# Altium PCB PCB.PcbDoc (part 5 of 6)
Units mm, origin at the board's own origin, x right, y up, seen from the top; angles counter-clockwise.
Board outline 101.6 x 101.61 mm, 4 copper layers (Top Layer, GND, POWER, Bottom Layer), stack 1.371 mm thick; 506 components, 346 nets, 1798 pads, 1471 vias.
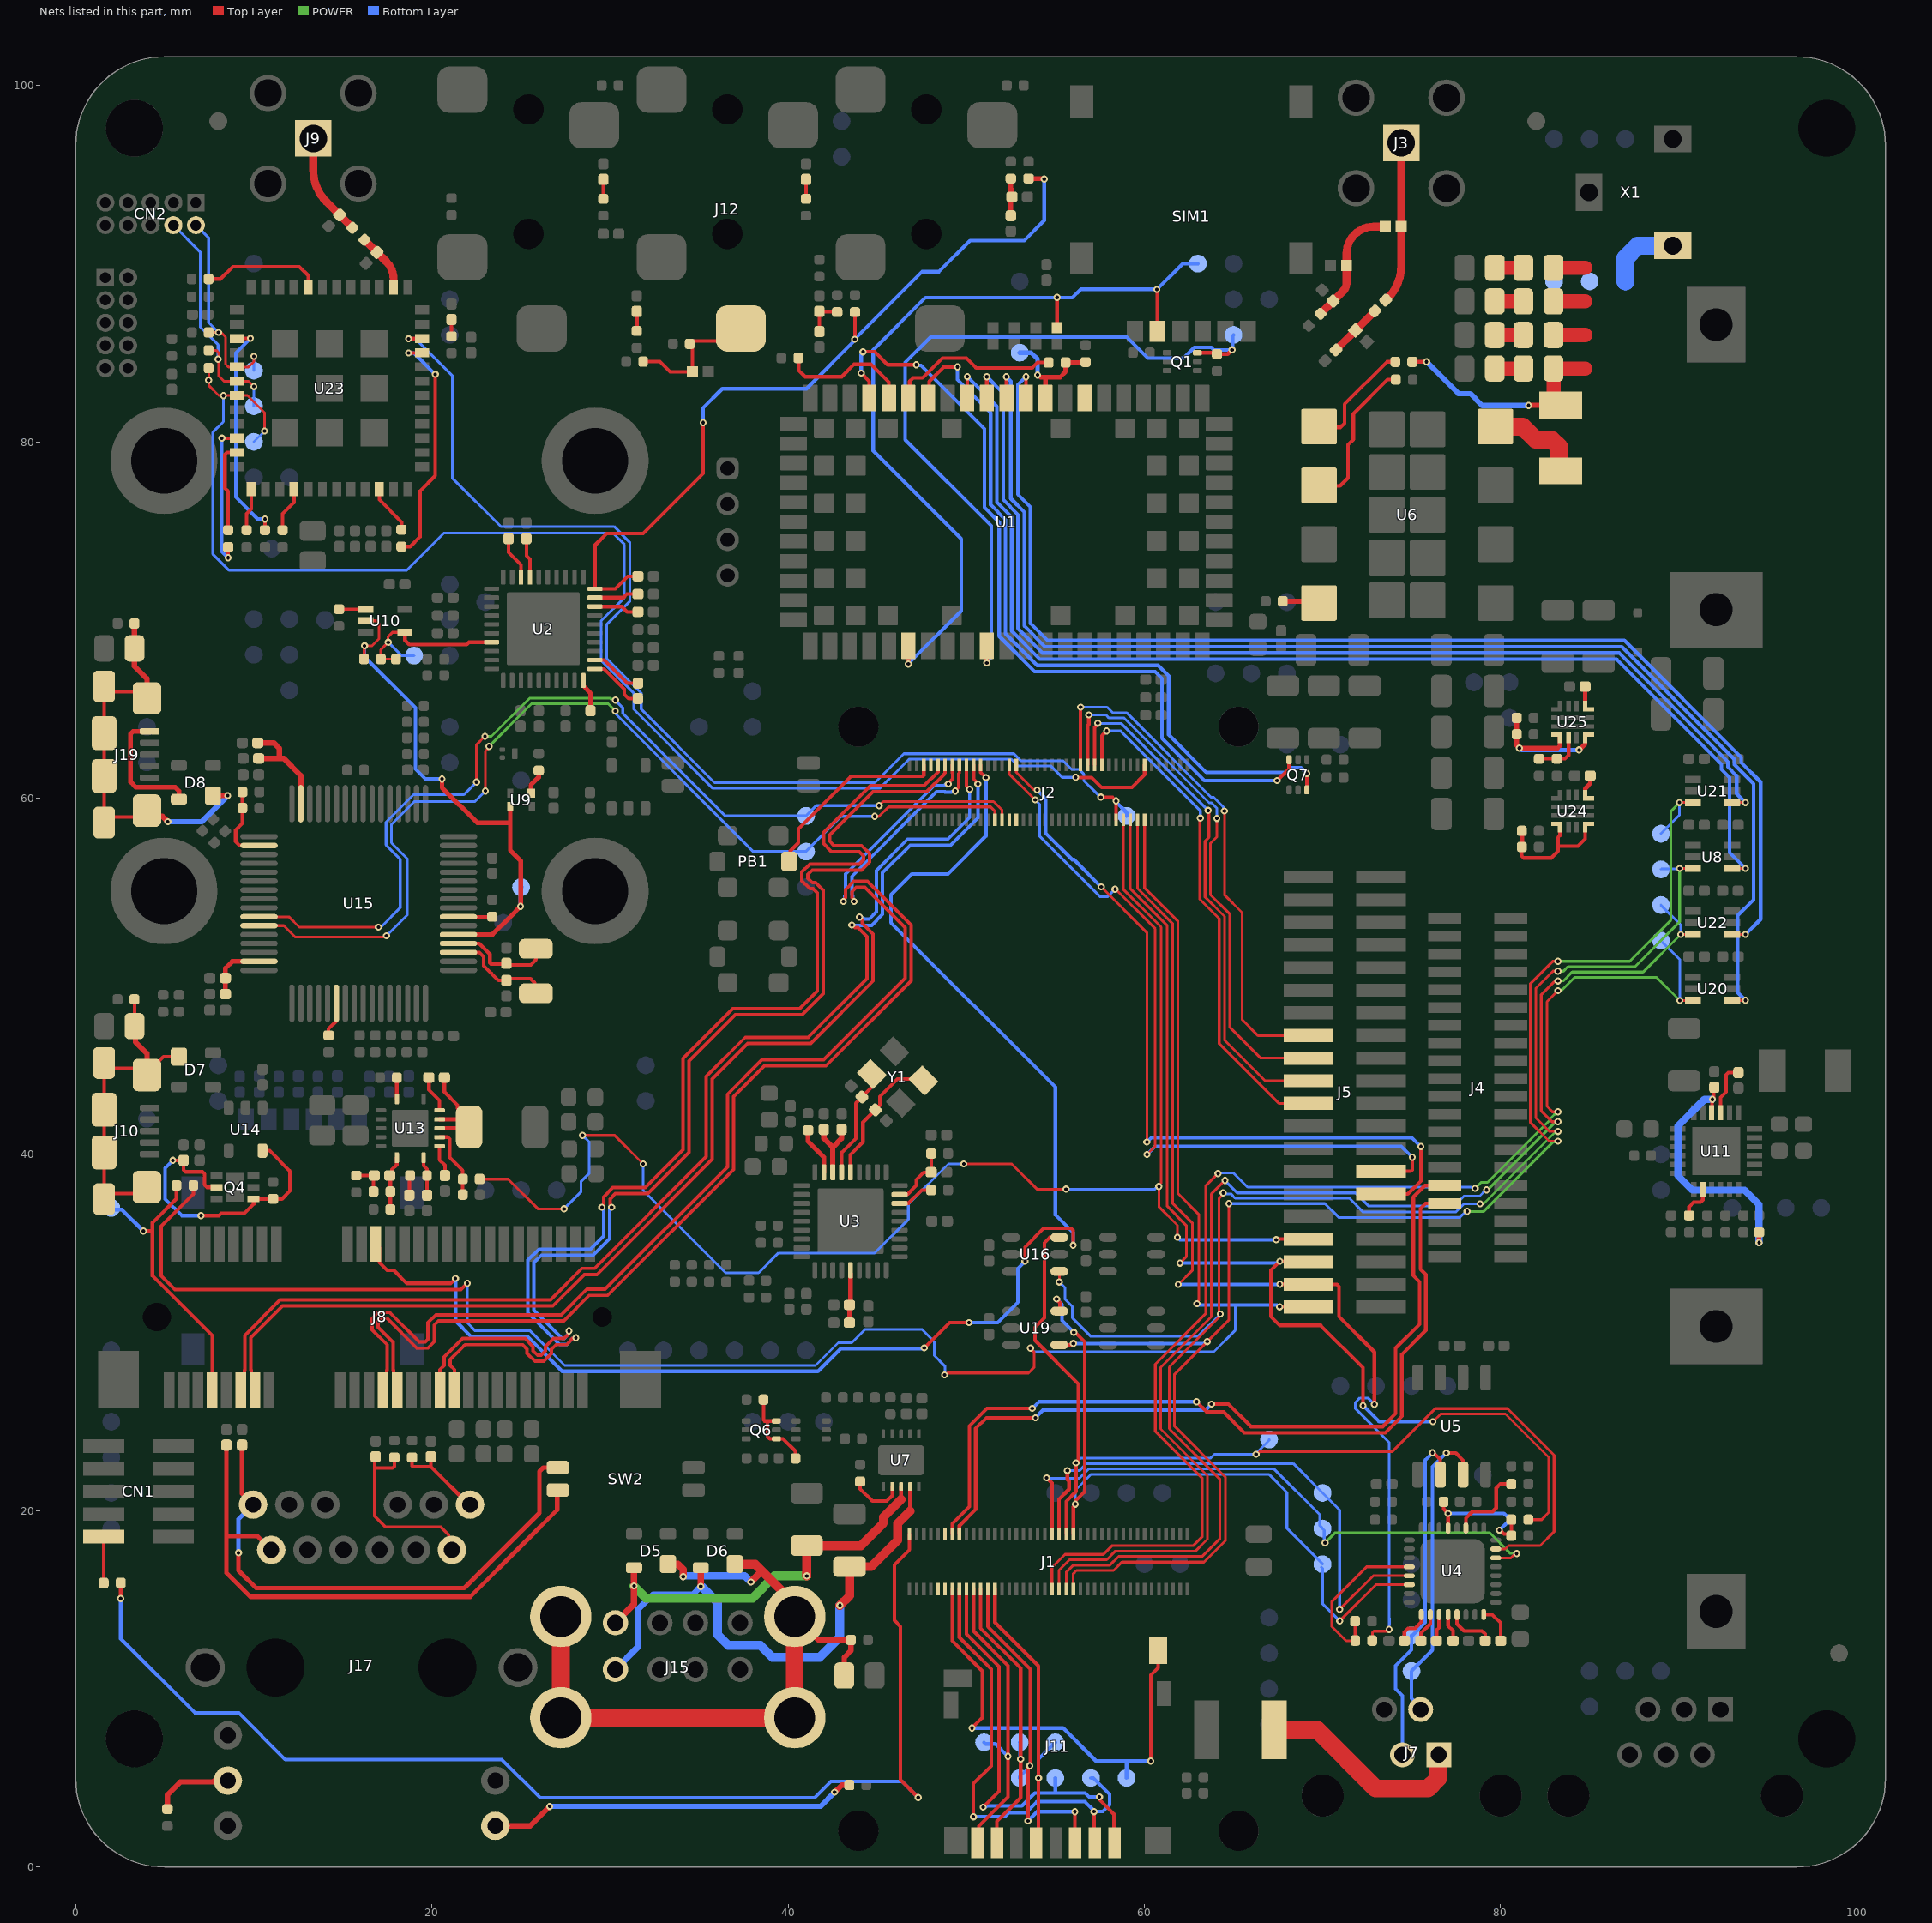
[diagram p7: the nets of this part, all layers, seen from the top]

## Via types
v1: diameter 0.4, hole 0.2, Top Layer to Bottom Layer, tented both sides, 1471 vias

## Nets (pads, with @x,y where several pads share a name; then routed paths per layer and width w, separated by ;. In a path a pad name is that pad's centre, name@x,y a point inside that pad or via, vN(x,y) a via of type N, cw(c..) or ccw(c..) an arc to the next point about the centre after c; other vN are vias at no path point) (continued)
JTAG.TRST_1: J1.80 R119.1 | length 68
  Top Layer w0.2: v1(2.528,15.071) R119.1@2.528,15.945 ; J1.80@46.81,18.685 46.81,18.376 46.81,17.81 45.963,16.963 45.963,13.845 46.308,13.5 46.308,4.892 v1(47.3,3.9)
  Bottom Layer w0.2: v1(2.528,15.071) 2.528,12.822 6.705,8.645 9.159,8.645 11.767,6.036 23.921,6.036 26.077,3.88 41.491,3.88 42.406,4.795 46.405,4.795 v1(47.3,3.9)
LICELL: J2.7
LORA_BOOT0_1: J2.67 R18.1 STM_BOOT0.X U23.43 | length 83.6
  Top Layer w0.15: R18.1@7.464,84.138 v1(7.464,83.457) 7.464,83.163 8.027,82.6 9.638,82.6 10.6,81.638 v1(10.6,80.6)
  Top Layer w0.2: v1(56.149,61.167) 56.155,61.16 57.04,61.16 57.6,60.6 59.294,60.6 60.01,61.316 J2.67@60.01,61.865
  Bottom Layer w0.15: v1(8.291,82.59) 8.291,81.129 7.7,80.539 7.7,73.69 8.597,72.794 18.594,72.794 20.674,74.873 30.164,74.873 30.805,74.231 30.805,71.261 29.501,69.956 29.501,67.721 31.333,65.888 31.333,64.98 35.753,60.56 45.16,60.56 46.79,62.19 52.517,62.19 52.908,61.799 54.761,61.799 55.393,61.167 v1(56.149,61.167) ; STM_BOOT0.X@10,80 v1(10.6,80.6)
LORA_IRQ_1: J2.60 LORA_IRQ.X U23.22 | length 64.5
  Top Layer w0.2: v1(18.687,85.788) 18.689,85.79 19.44,85.79 U23.22@19.45,85.8 ; v1(57.556,60.054) 57.578,60.032 58.216,60.032 v1(58.41,59.837) J2.60@58.41,58.785
  Bottom Layer w0.15: v1(18.687,85.788) 19.071,85.788 21.157,83.702 21.157,77.952 23.866,75.243 30.226,75.243 31.105,74.363 31.105,71.038 29.801,69.734 29.801,67.845 31.75,65.896 31.75,64.987 35.874,60.864 44.864,60.864 46.49,62.49 52.669,62.49 53.061,62.099 55.425,62.099 55.906,61.617 56.335,61.617 56.598,61.354 56.598,60.984 57.216,60.366 57.528,60.054 v1(57.556,60.054)
  Bottom Layer w0.2: v1(58.41,59.837) 58.41,59.783 59,59.193 LORA_IRQ.X@59,59
LoRa_SWCLK_6: CN2.4 LoRa_SWCLK.X R11.1 U23.42 | length 13.9
  Top Layer w0.15: R11.1@7.464,85.138 7.889,85.138 8.027,85 v1@8.027,84.674 ; v1(7.988,84.636) v1@8.027,84.674 ; v1(10,83.1) 9.7,83.4 U23.42@9.05,83.4 8.327,83.4 8.027,83.7 v1@8.027,84.674
  Bottom Layer w0.15: CN2.4@5.479,92.158 6.984,90.653 6.984,86.451 7.988,85.447 v1(7.988,84.636) ; LoRa_SWCLK.X@10,82 v1(10,83.1)
LoRa_SWDIO_6: CN2.2 LoRa_SWDIO.X R10.1 U23.41 | length 12
  Top Layer w0.15: R10.1@7.464,86.138 v1(8.016,86.138) 8.063,86.091 8.208,86.091 8.413,85.885 8.413,84.361 8.574,84.2 U23.41@9.05,84.2 9.7,84.2 10,84.5 v1(10,84.8)
  Bottom Layer w0.15: CN2.2@6.749,92.158 7.459,91.448 7.459,86.694 v1(8.016,86.138) ; LoRa_SWDIO.X@10,84 v1(10,84.8)
MCTS_1V8_5: U1.11 U20.4 | length 73.9
  Top Layer w0.15: U20.4@93,48.65 v1(93.75,48.65)
  Top Layer w0.2: U1.11@52.25,82.45 v1(52.25,83.65)
  Bottom Layer w0.2: v1(52.25,83.65) 52.5,83.4 52.5,76.812 53.25,76.062 53.25,69.666 54.416,68.5 86.8,68.5 93.132,62.168 93.132,61.873 94.2,60.805 94.2,54.3 93.3,53.4 93.3,49.1 v1(93.75,48.65)
MDTR_5: MDTR.X R7.2 R8.2 U1.9 | length 6.6
  Top Layer w0.25: v1(54,83.75) 54.041,83.75 54.165,83.625 54.45,83.625 ; U1.9@54.45,82.45 54.45,83.625 ; R7.2@56.7,84.475 56.688,84.462 55.587,84.462 R8.2@55.575,84.45 55.575,83.93 55.27,83.625 54.45,83.625
  Bottom Layer w0.25: MDTR.X@53,85 53.65,85 54,84.65 v1(54,83.75)
MICBIAS_4: C51.2 R36.1 R39.1 U2.20 | length 44.9
  Top Layer w0.2: C51.2@31.565,72.45 30.993,72.45 30.293,71.75 U2.20@29.15,71.75 29.15,74.187 29.817,74.855 31.857,74.855 35.225,78.223 v1(35.225,81.075) ; v1(43.734,85.753) 43.75,85.769 R36.1@43.75,87.275
  Top Layer w0.25: R39.1@53.5,94.775 54.35,94.775 v1(54.375,94.75)
  Bottom Layer w0.2: v1(35.225,81.075) 35.225,81.9 36.3,82.975 41.025,82.975 43.734,85.684 v1(43.734,85.753) 47.53,89.55 48.462,89.55 50.211,91.299 53.249,91.299 54.375,92.425 v1(54.375,94.75)
MRI_5: U1.7
MRST_1V8_5: Q7.6 U1.18 | length 45.8
  Top Layer w0.2: v1(44.1,83.85) 44.55,83.4 U1.18@44.55,82.45 ; v1(44.2,85.05) 44.86,85.05 45.589,84.321 v1(47.191,84.321) ; v1(67.448,60.982) 68.125,61.659 Q7.6@68.125,62.16
  Bottom Layer w0.2: v1(44.1,83.85) 44.1,84.896 44.2,84.996 v1(44.2,85.05) ; v1(47.191,84.321) 47.227,84.285 47.462,84.285 50.903,80.844 51.02,80.727 51.02,76.312 51.85,75.482 51.85,69.087 53.837,67.1 60.592,67.1 60.983,66.709 60.983,63.359 63.359,60.982 v1(67.448,60.982)
MRTS_1V8_5: U1.10 U22.4 | length 70.8
  Top Layer w0.15: U22.4@93,52.35 v1(93.75,52.35) U22.4@93,52.35
  Top Layer w0.2: U1.10@53.35,82.45 v1(53.35,83.65)
  Bottom Layer w0.2: v1(53.35,83.65) 52.9,83.2 52.9,77.052 53.6,76.352 53.6,69.811 54.561,68.85 86.945,68.85 93.509,62.286 93.509,61.991 94.6,60.9 94.6,53.2 v1(93.75,52.35)
MRX_1V8_5: U1.13 U8.4 | length 66.6
  Top Layer w0.15: U8.4@93,56.05 v1(93.75,56.05)
  Top Layer w0.2: U1.13@50.05,82.45 50.054,82.453 v1(50.054,83.654)
  Bottom Layer w0.2: v1(50.054,83.654) 51.72,81.987 51.72,76.602 52.55,75.772 52.55,69.376 54.127,67.8 86.51,67.8 92.405,61.905 92.405,61.61 92.858,61.158 92.858,56.942 v1(93.75,56.05)
MTX_1V8_5: U1.12 U21.4 | length 62.5
  Top Layer w0.15: U21.4@93,59.75 v1(93.75,59.75)
  Top Layer w0.2: U1.12@51.15,82.45 v1(51.15,83.65)
  Bottom Layer w0.2: v1(51.15,83.65) 52.07,82.73 52.07,76.747 52.9,75.917 52.9,69.521 54.271,68.15 86.655,68.15 92.755,62.05 92.755,61.755 93.25,61.26 93.25,60.25 v1(93.75,59.75)
Net12MHz_CLK_X: 12MHz_CLK.X R60.1 U9.3 U10.2 U15.5 | length 29.5
  Top Layer w0.15: R60.1@16.185,67.805 16.2,67.82 16.2,68.534 v1(16.216,68.55) 16.645,68.55 17.032,68.937 17.032,69.808 16.885,69.955 U10.2@16.285,69.955
  Top Layer w0.26: v1(20.57,61.075) 20.57,60.588 22.54,58.618 24.305,58.618 24.395,58.708 ; U15.5@21.489,52.338 23.391,52.338 24.41,53.357 v1(24.977,53.924) 24.977,56.479 24.395,57.061 24.395,58.708 ; U9.3@24.395,59.525 24.395,58.708
  Bottom Layer w0.2: v1(16.216,68.55) 16.216,67.929 19.07,65.075 19.07,61.638 19.633,61.075 v1(20.57,61.075)
  Bottom Layer w0.26: v1(24.977,53.924) 24.989,53.936 24.989,54.989 12MHz_CLK.X@25,55
NetAUDIO_MCLK_X: AUDIO_MCLK.X R60.2 R61.2 U2.37 U10.4 | length 10.6
  Top Layer w0.15: R61.2@18.085,67.805 17.235,67.805 17.135,67.905 17.135,68.335 v1(17.543,68.743) 17.543,69.063 17.785,69.305 U10.4@18.485,69.305
  Top Layer w0.2: U10.4@18.485,69.305 18.485,68.855 18.726,68.614 21.952,68.614 22.088,68.75 U2.37@23.35,68.75
  Bottom Layer w0.15: v1(17.543,68.743) 18.286,68 AUDIO_MCLK.X@19,68
NetC8_2: C8.2 C9.1 L1.2 | length 3.1
  Top Layer w0.425: C8.2@70.758,85.158 L1.2@71.85,86.25 C9.1@72.938,87.338
NetC9_2: C9.2 J3.1 L2.2 | length 9.1
  Top Layer w0.447: C9.2@73.553,87.953 73.678,88.078 ccw(c71.882,89.874) 74.422,89.874 L2.2@74.422,92.078 J3.1@74.422,96.774
NetC10_2: C10.2 D4.C L2.1 R6.2 | length 7
  Top Layer w0.447: R6.2@69.886,87.186 70.4,87.7 C10.2@70.6,87.9 71.023,88.323 71.159,88.459 ccw(c70.7,88.917) 71.348,88.885 cw(c72.463,88.831) 71.349,88.913 71.35,88.923 71.35,90.55 cw(c72.878,90.55) 72.878,92.078 L2.1@73.522,92.078
NetC16_2: C16.2 R15.1 U23.26 | length 3.3
  Top Layer w0.44: R15.1@16.216,91.334 C16.2@16.92,90.63 17.438,90.112 cw(c16.445,89.118) 17.85,89.118 U23.26@17.85,88.65
NetC17_2: C17.2 J9.1 R15.2 | length 5.8
  Top Layer w0.44: J9.1@13.335,97.028 13.335,95.267 ccw(c15.875,95.267) 14.079,93.471 C17.2@14.821,92.729 R15.2@15.545,92.006
NetC20_1: C20.1 J17.6 SW2.2 | length 32.3
  Top Layer w0.25: C20.1@8.459,23.688 8.459,18.568 ; J17.6@10.975,17.8 10.207,18.568 8.459,18.568 ; SW2.2@27.065,21.155 27.029,21.119 27.029,20.049 25.119,18.138 22.148,15.168 9.806,15.168 8.459,16.514 8.459,18.568
NetC21_1: C21.1 J17.7 R94.1 | length 5.2
  Top Layer w0.2: R94.1@18.891,22.99 18.891,22.527 18.949,22.469 19.944,22.469 ; C21.1@19.941,23.03 19.941,22.472 19.944,22.469 ; J17.7@22.14,20.34 22.072,20.34 19.944,22.469
NetC22_1: C22.1 R26.2 | length 1.1
  Top Layer w0.2: R26.2@41,93.637 C22.1@41,94.727
NetC23_1: C23.1 R27.2 | length 1.1
  Top Layer w0.25: R27.2@31.5,86.225 C23.1@31.5,87.315
NetC31_1: C31.1 U2.12 | length 3
  Top Layer w0.2: U2.12@29.15,67.75 29.663,67.75 30.963,66.45 C31.1@31.565,66.45
NetC31_2: C31.2 U2.11 | length 3.3
  Top Layer w0.2: U2.11@29.15,67.25 29.668,67.25 30.229,66.689 30.806,66.112 30.806,65.826 31.052,65.58 C31.2@31.565,65.58
NetC33_1: C33.1 U2.10 | length 1.9
  Top Layer w0.25: U2.10@28.5,66.6 28.5,66.3 28.9,65.9 C33.1@28.9,64.9
NetC34_2: C34.2 R65.2 U13.8 | length 2.2
  Top Layer w0.2: U13.8@19.53,39.815 19.53,39.371 19.725,39.176 R65.2@19.725,38.815 19.73,38.81 C34.2@19.73,37.715
NetC38_1: C38.1 R32.2 | length 0.9
  Top Layer w0.2: R32.2@21.1,85.925 C38.1@21.1,86.865
NetC41_1: C41.1 R33.2 | length 1.1
  Top Layer w0.2: R33.2@29.622,93.637 C41.1@29.622,94.727
NetC42_2: C42.2 C44.2 R37.1 | length 2.1
  Top Layer w0.2: C42.2@41.75,86.185 C44.2@41.75,87.315 41.77,87.295 42.73,87.295 R37.1@42.75,87.275
NetC45_1: C45.1 C47.2 R38.1 | length 3.1
  Top Layer w0.2: R38.1@52.5,94.775 52.5,94.274 52.565,94.209 C45.1@52.565,93.75
  Top Layer w0.25: C47.2@52.5,92.685 R38.1@52.5,94.775
NetC46_1: C46.1 U2.27 | length 2.2
  Top Layer w0.19: C46.1@25.3,74.565 25.3,73.6 25.5,73.4 U2.27@25.5,72.4
NetC48_1: C48.1 U2.18 | length 2.5
  Top Layer w0.2: U2.18@29.15,70.75 30.655,70.75 30.955,70.45 C48.1@31.565,70.45
NetC49_1: C49.1 U2.19 | length 2.5
  Top Layer w0.2: U2.19@29.15,71.25 30.739,71.25 30.939,71.45 C49.1@31.565,71.45
NetC50_1: C50.1 U2.28 | length 2.5
  Top Layer w0.19: C50.1@24.3,74.565 24.3,73.8 25,73.1 U2.28@25,72.4
NetC52_1: C52.1 J17.12 SW2.1 | length 30
  Top Layer w0.25: v1(9.139,17.638) 9.139,16.648 10.134,15.654 21.823,15.654 26.033,19.864 26.033,22.206 26.247,22.42 26.86,22.42 SW2.1@26.865,22.425 ; C52.1@9.339,23.688 9.339,20.961 J17.12@9.96,20.34
  Bottom Layer w0.25: v1(9.139,17.638) 9.139,19.519 J17.12@9.96,20.34
NetC53_1: C53.1 U4.29 | length 2.7
  Top Layer w0.2: U4.29@77.55,14.175 77.55,13.65 77.944,13.256 78.949,13.256 79.13,13.075 C53.1@79.13,12.7
NetC53_2: C53.2 U4.32 | length 2.1
  Top Layer w0.2: U4.32@79.05,14.175 79.525,14.175 80,13.7 C53.2@80,12.7
NetC54_1: C54.1 U4.27 | length 1.5
  Top Layer w0.2: C54.1@76.4,12.7 76.4,13.3 76.55,13.45 U4.27@76.55,14.175
NetC54_2: C54.2 U4.26 | length 1.7
  Top Layer w0.2: C54.2@75.53,12.7 75.53,13.13 76.05,13.65 U4.26@76.05,14.175
NetC55_1: C55.1 U4.25 | length 2.1
  Top Layer w0.2: C55.1@74.6,12.7 74.6,13.2 74.8,13.4 75.2,13.4 75.55,13.75 U4.25@75.55,14.175
NetC56_1: C56.1 U4.28 | length 1.6
  Top Layer w0.2: U4.28@77.05,14.175 77.05,13.55 77.33,13.27 C56.1@77.33,12.7
NetC65_2: C65.2 U24.7 | length 1.2
  Top Layer w0.25: U24.7@84.738,60.159 84.738,60.533 85.038,60.833 C65.2@85.038,61.259
NetC66_2: C66.2 C67.2 U3.34 | length 3.8
  Top Layer w0.3: C67.2@42,41.4 42,40.9 42.5,40.4 ; U3.34@42.5,39 42.5,40.4 ; C66.2@43,41.4 43,40.9 42.5,40.4
NetC68_2: C68.2 C69.2 U3.14 | length 3.8
  Top Layer w0.2: C68.2@43.435,30.55 C69.2@43.435,31.55
  Top Layer w0.25: C68.2@43.435,30.55 43.435,31.491 43.5,31.556 U3.14@43.5,33.3
NetC78_2: C78.2 D5.4 J15.1 U7.8 | length 23
  Top Layer w0.2: 46.339,20.638 U7.8@46.339,21.363
  Top Layer w0.35: J15.1@30.3,13.71 31.345,14.755 v1(31.345,15.778) D5.4@31.345,16.8
  Top Layer w0.5: v1(41.039,16.338) C78.2@41.039,18.038 44.073,18.038 45.339,19.304 45.339,19.637 46.339,20.638
  POWER w0.5: v1(31.345,15.778) 32.023,15.1 38.002,15.1 39.239,16.338 v1(41.039,16.338)
NetC79_2: C79.2 D6.4 J15.5 U7.9 | length 30.7
  Top Layer w0.2: 46.839,19.978 U7.9@46.839,21.363
  Top Layer w0.35: D6.4@35.095,16.8 35.095,15.752 v1(35.097,15.75)
  Top Layer w0.5: v1(42.901,14.686) 43.439,15.225 C79.2@43.439,16.863 44.664,16.863 46.142,18.34 46.142,19.28 46.839,19.978
  Bottom Layer w0.35: J15.5@30.3,11.09 31.561,12.351 31.561,14.453 32.408,15.3 34.647,15.3 v1(35.097,15.75)
  Bottom Layer w0.5: v1@35.2,15.7 36.039,14.861 36.039,13.038 36.639,12.438 38.439,12.438 39.113,11.764 41.188,11.764 41.191,11.767 41.768,11.767 42.901,12.899 v1(42.901,14.686)
NetC80_2: C80.2 D5.1 D6.1 J15.Shell R59.2 | length 42.1
  Top Layer w0.3: J15.Shell@40.37,14.06 41.68,12.75 R59.2@43.525,12.75 43.525,12.147 43.15,11.772 C80.2@43.15,10.75
  Top Layer w0.4: D5.1@33.255,17 33.808,17 34.108,16.7 v1(34.108,16.3) ; v1(37.908,16) 38.529,16.621
  Top Layer w0.5: D6.1@37.005,17 38.15,17 38.529,16.621 J15.Shell@40.37,14.78
  Top Layer w0.7: J15.Shell@40.37,14.06 J15.Shell@40.37,14.78
  Top Layer w1: J15.Shell@27.23,14.06 J15.Shell@27.23,8.38 J15.Shell@40.37,8.38 J15.Shell@40.37,14.06
  Bottom Layer w0.25: J15.Shell@40.084,14.06 J15.Shell@40.57,14.06
  Bottom Layer w0.4: v1(34.108,16.3) 34.153,16.345 37.563,16.345 v1(37.908,16)
NetC81_1: C81.1 J17.1 R93.1 | length 10.5
  Top Layer w0.19: C81.1@16.841,23.03 16.791,22.98 16.791,22.396 ; R93.1@17.891,22.99 17.891,22.499 17.787,22.396 16.791,22.396 ; J17.1@21.125,17.8 20.941,17.984 20.941,18.639 20.491,19.09 17.391,19.09 16.791,19.69 16.791,22.396
NetC82_2: C82.2 R65.1 | length 1.1
  Top Layer w0.2: C82.2@18.73,37.715 18.73,38.77 R65.1@18.775,38.815
NetC84_1: C84.1 U11.21 | length 3
  Top Layer w0.2: U11.21@92.35,42.335 92.35,43.193 92.67,43.512 92.67,44.478 92.787,44.595 C84.1@93.35,44.595
NetC89_2: C89.2 R54.1 U3.26 | length 3.5
  Top Layer w0.2: U3.26@46.25,37.75 46.265,37.765 46.698,37.765 47.2,38.268 47.2,38.575 47.46,38.835 47.612,38.987 48.012,38.987 C89.2@48.027,39.002 R54.1@48.026,40.047
NetC90_2: C90.2 U3.33 Y1.3 | length 6.3
  Top Layer w0.2: U3.33@43,39 43,40.1 43.789,40.889 43.789,42.874 C90.2@44.14,43.225 44.741,43.825 44.741,44.462 Y1.3@44.692,44.511
NetC91_2: C91.2 U3.32 Y1.1 | length 7.8
  Top Layer w0.2: U3.32@43.5,39 43.5,40 44.195,40.695 44.195,41.803 C91.2@44.892,42.501 45.142,42.751 45.142,43.242 46.128,44.228 47.52,44.228 Y1.1@47.591,44.157
NetC93_1: C93.1 U13.13 | length 2.1
  Top Layer w0.2: C93.1@19.83,44.315 19.83,43.632 20.43,43.032 U13.13@20.43,42.465
NetC93_2: C93.2 L6.1 U13.11 U13.12 | length 5.9
  Top Layer w0.2: C93.2@20.7,44.315 20.7,43.508 21.439,42.769 21.439,42.601 L6.1@21.688,42.352
  Top Layer w0.25: U13.11@20.43,41.465 22.017,41.465 L6.1@22.089,41.538 21.662,41.965 U13.12@20.43,41.965
NetC107_1: C107.1 U15.3 Y3.2 | length 6.1
  Top Layer w0.2: U15.3@21.489,51.338 22.656,51.338 22.9,51.094 22.9,50.593 23.32,50.173 23.73,49.763 C107.1@24.178,49.763 24.276,49.861 25.535,49.861 25.761,49.635 25.761,49.04 Y3.2@25.842,48.96
NetC108_2: C108.2 C109.2 U15.47 | length 3.5
  Top Layer w0.26: C109.2@8.4,49 C108.2@8.4,49.9 8.4,50.448 8.789,50.838 U15.47@10.289,50.838
NetC110_2: C110.2 C111.2 U15.31 | length 6.3
  Top Layer w0.3: C110.2@10.22,63.093 11.132,63.093 11.437,62.788 11.437,62.227 ; C111.2@10.27,62.227 11.437,62.227 ; U15.31@12.639,59.688 12.639,60.72 12.643,60.724 12.643,61.269 11.686,62.227 11.437,62.227
NetC112_1: C112.1 U15.4 Y3.1 | length 5.9
  Top Layer w0.2: U15.4@21.489,51.838 22.651,51.838 23.25,51.238 23.25,50.752 23.309,50.693 C112.1@24.178,50.693 ; C112.1@24.178,50.723 24.266,50.635 25.545,50.635 25.847,50.937 25.847,51.532 Y3.1@25.835,51.543
NetC116_1: C116.1 C121.2 | length 1.5
  Top Layer w0.8: C121.2@79.77,87.879 C116.1@81.27,87.879
NetC117_2: C117.2 Q4.A Q4.G R89.1 U14.5 | length 17.3
  Top Layer w0.2: v1(5.455,39.665) C117.2@6.055,39.665 6.055,39.137 6.172,39.019 7.117,39.019 7.235,38.902 7.235,38.299 7.379,38.155 Q4.G@7.905,38.155 ; v1(7.035,36.568) 8.051,36.568 8.173,36.689 9.473,36.689 9.985,37.201 Q4.A@9.985,37.505 R89.1@10.985,37.505 ; U14.5@10.485,40.205 10.886,40.205 12.025,39.066 12.025,37.95 11.58,37.505 R89.1@10.985,37.505
  Bottom Layer w0.2: v1(5.455,39.665) 5.025,39.235 5.025,37.495 5.952,36.568 v1(7.035,36.568)
NetC118_1: C118.1 C122.2 | length 1.5
  Top Layer w0.8: C122.2@79.77,89.761 C118.1@81.27,89.761
NetC119_1: C119.1 C123.2 | length 1.5
  Top Layer w0.8: C123.2@79.77,85.997 C119.1@81.27,85.997
NetC120_1: C120.1 C124.2 | length 1.5
  Top Layer w0.8: C124.2@79.77,84.115 C120.1@81.27,84.115
NetC127_1: C127.1 U13.9 | length 1.8
  Top Layer w0.2: U13.9@20.43,40.465 20.43,39.691 20.73,39.391 C127.1@20.73,38.815
NetC128_1: C128.1 R67.2 R68.1 U13.7 | length 3.1
  Top Layer w0.2: R67.2@17.67,36.915 R68.1@17.67,37.915 17.67,38.775 C128.1@17.63,38.815 17.751,38.936 17.751,39.146 18.03,39.426 U13.7@18.03,39.815
NetC128_2: C128.2 R64.1 R68.2 | length 1.9
  Top Layer w0.2: R64.1@15.755,38.815 C128.2@16.76,38.815 16.72,38.775 R68.2@16.72,37.915
NetC147_2: C147.2 U25.7 | length 1.1
  Top Layer w0.25: U25.7@84.738,65.159 C147.2@84.738,66.259
NetC157_2: C157.2 D7.1 J10.M1 J10.M2 J10.M3 J10.M4 J10.M5 J10.M6 R84.2 | length 19.7
  Top Layer w0.2: C157.2@3.3,47.2 R84.2@3.3,48.7 ; J10.M1@3.949,44.508 3.636,44.822 1.908,44.822 J10.M2@1.6,45.13 J10.M5@1.6,42.51 J10.M6@1.6,40.11 J10.M3@1.6,37.49 1.908,37.798 3.636,37.798 J10.M4@4,38.163 ; J10.M1@4,44.458 J10.M1@4.101,44.558 ; J10.M1@4.05,44.609 4.931,45.49 D7.1@5.795,45.49
  Top Layer w0.3: C157.2@3.3,47.2 3.351,47.149 3.351,46.315 4,45.666 J10.M1@4,44.458
NetC158_2: C158.2 D8.1 J19.M1 J19.M2 J19.M3 J19.M4 J19.M5 J19.M6 R85.2 | length 22.7
  Top Layer w0.19: J19.M4@3.636,58.934 1.908,58.934 J19.M3@1.6,58.626 J19.M6@1.6,61.246 J19.M5@1.6,63.646 J19.M2@1.6,66.266 1.908,65.958 J19.M1@3.636,65.958
  Top Layer w0.3: R85.2@3.3,69.8 C158.2@3.3,68.4 3.3,67.4 4,66.7 J19.M1@4,65.594 ; J19.M4@4,59.299 4.316,58.983 4.862,58.983 v1(5.17,58.675) ; D8.1@7.703,60.138 v1(8.533,60.138)
  Bottom Layer w0.3: v1(5.17,58.675) 7.07,58.675 v1(8.533,60.138)
NetCANH_X: CANH.X J7.2 U5.7 | length 17.3
  Top Layer w0.2: v1(76.949,23.238) 77.485,23.238 77.885,22.838 U5.7@77.885,22.025
  Bottom Layer w0.2: J7.2@75.51,8.84 75.51,8.951 75,9.461 CANH.X@75,11 76.18,12.18 76.18,22.469 v1(76.949,23.238)
NetCANL_X: CANL.X J7.3 U5.6 | length 19.4
  Top Layer w0.2: v1(76.17,23.25) 76.237,23.25 76.615,22.872 U5.6@76.615,22.025
  Bottom Layer w0.2: J7.3@74.49,6.3 74.49,9.61 74.1,10 74.1,11.295 75,12.195 CANL.X@75,13 ; CANL.X@75.036,13 75.762,13.725 75.762,22.842 v1(76.17,23.25)
NetCN1_9: CN1.9 R119.2 | length 2.6
  Top Layer w0.2: R119.2@1.578,15.945 CN1.9@1.578,18.545
NetD8_4: D8.4 J19.1 | length 7.2
  Top Layer w0.26: J19.1@4.16,63.746 3.226,63.746 3.085,63.605 3.085,60.905 3.385,60.605 5.585,60.605 5.793,60.397 D8.4@5.793,59.938
NetD12_C: D12.C J12.4 R22.1 R23.2 | length 7.9
  Top Layer w0.2: R23.2@31.859,84.5 32.8,84.5 33.375,83.925 D12.C@34.625,83.925 34.625,85.35 R22.1@34.475,85.5 34.63,85.655 36.633,85.655 J12.4@37.338,86.36
NetF1_1: F1.1 J7.1 | length 12.1
  Top Layer w1: F1.1@67.3,7.7 69.7,7.7 73,4.4 75.914,4.4 76.5,4.986 76.5,6.27 J7.1@76.53,6.3
NetJ8_7: J8.7 PCIE_CLKREQ.X R63.2 | length 16.3
  Top Layer w0.2: v1(3.8,35.7) 4.31,35.7 ; R63.2@5.655,38.265 5.655,37.518 4.31,36.174 4.31,35.7 ; J8.7@7.657,26.777 7.657,29.835 4.31,33.181 4.31,35.7
  Bottom Layer w0.2: PCIE_CLKREQ.X@2,37 2.1,36.9 2.6,36.9 v1(3.8,35.7)
NetJ17_14: J17.14 R96.1 | length 20.8
  Top Layer w0.3: J17.14@23.56,2.31 25.518,2.31 v1(26.608,3.4) ; v1(42.608,4.2) 43.008,4.6 R96.1@43.433,4.6
  Bottom Layer w0.3: v1(26.608,3.4) 41.808,3.4 v1(42.608,4.2)
NetJ17_16: J17.16 R95.1 | length 3.8
  Top Layer w0.3: R95.1@5.149,3.256 5.149,4.049 5.874,4.774 7.714,4.774 J17.16@7.79,4.85
NetL3_2: L3.2 U6.8 | length 5.4
  Top Layer w1: U6.8@79.705,80.85 81.235,80.85 81.975,80.11 82.875,80.11 83.275,79.71 L3.2@83.275,78.36
NetPB1_6: J2.5 PB1.6 | length 10.9
  Top Layer w0.2: PB1.6@40.054,56.438 40.125,56.508 40.125,57.039 40.57,57.484 40.57,58.269 43.523,61.223 47.551,61.223 47.61,61.281 J2.5@47.61,61.865
NetQ1_6: Q1.6 R1.1 SIM_DET.X U1.42 | length 42.6
  Top Layer w0.2: Q1.6@62.975,85 64,85 R1.1@64.075,84.925 64.679,84.925 v1(64.917,85.162)
  Top Layer w0.25: v1(51.15,67.589) U1.42@51.15,68.55
  Bottom Layer w0.2: v1(51.15,67.589) 51.15,67.643 51.4,67.893 51.4,75.285 46.572,80.113 46.572,84.45 47.997,85.875 59.012,85.875 60.187,84.7 62.2,84.7 62.8,85.3 63.763,85.3 63.9,85.162 v1(64.917,85.162) 64.955,85.201 64.955,85.955 SIM_DET.X@65,86
NetQ6_4: Q6.4 Q6.6 R112.1 R113.2 | length 5.1
  Top Layer w0.2: R113.2@38.616,26.238 38.616,25.09 38.668,25.038 38.84,25.038 ; Q6.6@39.341,25.038 38.84,25.038 ; R112.1@40.416,22.938 40.416,23.335 39.713,24.038 38.969,24.038 38.84,24.167 38.84,25.038
NetR8_1: R8.1 U1.16 | length 9.7
  Top Layer w0.2: U1.16@46.75,82.45 46.816,82.516 46.816,83.383 47.026,83.593 47.543,83.593 48.653,84.702 50,84.702 50.552,84.15 53.7,84.15 54,84.45 R8.1@54.625,84.45 R8.1@54.621,84.446
NetR9_1: R9.1 U23.32 | length 6.8
  Top Layer w0.2: R9.1@7.459,89.138 8.129,89.138 8.812,89.821 12.56,89.821 13.05,89.331 U23.32@13.05,88.65
NetR12_2: R12.2 U23.39 | length 12.8
  Top Layer w0.2: U23.39@9.05,85.8 9.8,85.8 v1(9.81,85.81) ; R12.2@10.624,75.04 v1(10.624,75.657)
  Bottom Layer w0.2: v1@9.8,85.8 8.986,84.986 8.986,76.895 10.224,75.657 v1(10.624,75.657)
NetR13_1: R13.1 U23.4 | length 2.6
  Top Layer w0.2: R13.1@11.615,75.04 11.615,75.955 12.26,76.6 12.26,77.34 U23.4@12.25,77.35
NetR16_1: R16.1 U23.10 | length 2.8
  Top Layer w0.2: U23.10@17.05,77.35 17.05,76.749 18.291,75.508 R16.1@18.291,75.065
NetR16_2: R16.2 U23.21 | length 13.5
  Top Layer w0.2: R16.2@18.291,74.115 18.776,74.115 19.324,74.664 19.324,76.423 19.331,76.429 19.331,77.23 20.191,78.09 v1(20.191,83.79) ; v1@18.689,84.99 U23.21@19.44,84.99
  Bottom Layer w0.2: v1(18.687,84.988) 18.993,84.988 v1(20.191,83.79)
NetR19_1: R19.1 U23.47 | length 5
  Top Layer w0.2: R19.1@8.558,75.04 8.558,77.223 8.373,77.407 8.373,79.28 8.493,79.4 U23.47@9.05,79.4
NetR19_2: R19.2 U23.46 | length 8.3
  Top Layer w0.2: v1(8.2,80.2) U23.46@9.05,80.2 ; v1(8.558,73.49) R19.2@8.558,74.09
  Bottom Layer w0.2: v1(8.2,80.2) 8.2,73.848 v1(8.558,73.49)
NetR20_1: R20.1 U1.17 | length 7.5
  Top Layer w0.2: R20.1@40.575,84.7 40.6,84.675 40.6,84 40.95,83.65 43,83.65 43.7,84.35 44.643,84.35 45.65,83.343 U1.17@45.65,82.45
NetR43_1: R43.1 R44.2 U4.20 | length 9.3
  Top Layer w0.15: R43.1@71.83,13.8 71.827,13.797 71.827,12.723 71.85,12.7 71.33,12.7 70.513,13.517 70.513,14.883 72.48,16.85 U4.20@74.875,16.85
NetR45_1: R45.1 U4.11 | length 4.6
  Top Layer w0.2: U4.11@78.05,19.025 78.05,19.581 78.423,19.954 79.554,19.954 79.75,20.15 79.75,21.275 79.975,21.5 R45.1@80.6,21.5
NetR48_1: R48.1 R51.2 R52.2 U4.13 | length 7.7
  Top Layer w0.2: R48.1@76.8,20.5 76.8,20.1 v1(77.05,19.85) U4.13@77.05,19.025 ; v1(79.93,18.9) 79.968,18.862 80.022,18.862 80.189,18.696 80.504,18.696 R52.2@80.6,18.6 R51.2@80.6,19.5
  Bottom Layer w0.2: v1(77.05,19.85) 80.18,19.85 80.43,19.6 80.43,19.4 v1(79.93,18.9)
NetR50_2: R50.2 U6.4 | length 2.2
  Top Layer w0.3: R50.2@67.765,71.046 70.005,71.046 U6.4@70.005,71.05
NetR53_1: R53.1 U3.25 | length 2.1
  Top Layer w0.2: U3.25@46.25,37.25 46.265,37.265 46.763,37.265 47.498,38 R53.1@48.025,38
NetR55_1: R55.1 U3.35 | length 2.7
  Top Layer w0.26: R55.1@41.12,41.36 41.12,40.727 42,39.847 U3.35@42,39
NetR57_1: R57.1 U9.1 | length 1.5
  Top Layer w0.26: U9.1@25.555,60.275 25.555,60.735 25.995,61.175 R57.1@25.995,61.55
NetR58_1: R58.1 U7.7 | length 3.1
  Top Layer w0.2: R58.1@44.039,21.638 44.039,21.226 44.727,20.538 45.532,20.538 45.839,20.845 U7.7@45.839,21.363
NetR62_1: R62.1 U10.1 | length 1.5
  Top Layer w0.15: R62.1@14.785,70.605 U10.1@16.285,70.605
NetR66_2: R66.2 U13.1 | length 1.2
  Top Layer w0.2: U13.1@18.03,43.115 R66.2@18.03,44.315
NetR69_2: R69.2 R87.1 U13.10 | length 4
  Top Layer w0.2: U13.10@20.43,40.965 20.439,40.973 20.883,40.973 21,40.856 21,39.825 21.73,39.095 R69.2@21.73,38.615 R87.1@21.73,37.745
NetR70_2: R70.2 U11.8 | length 2
  Top Layer w0.2: R70.2@90.584,36.575 90.584,37.066 90.838,37.32 91.233,37.32 91.35,37.437 U11.8@91.35,38.025
NetR77_2: R77.2 U6.2 | length 8.7
  Top Layer w0.2: U6.2@69.805,77.55 69.824,77.531 70.988,77.531 71.427,77.969 71.427,79.826 71.733,80.132 71.733,81.57 73.652,83.49 R77.2@74.116,83.49
NetR80_1: R80.1 U15.54 | length 2
  Top Layer w0.2: R80.1@14.194,46.688 14.194,47.043 14.62,47.469 14.62,48.468 U15.54@14.639,48.488
NetR83_1: R83.1 U15.7 | length 1.9
  Top Layer w0.2: U15.7@21.489,53.338 R83.1@23.389,53.338
NetR86_1: R86.1 U23.1 | length 2.4
  Top Layer w0.2: R86.1@9.591,75.04 9.591,75.956 9.85,76.215 U23.1@9.85,77.35
NetR88_1: R88.1 R122.2 U25.2 | length 2.7
  Top Layer w0.2: R88.1@82.168,62.209 83.168,62.209 83.618,62.209 83.813,62.404 U25.2@83.813,63.37
NetR111_2: R111.2 U6.1 | length 6.5
  Top Layer w0.2: U6.1@69.805,80.85 69.845,80.81 71.004,80.81 71.237,81.043 71.237,82.112 73.615,84.49 R111.2@74.091,84.49
NetR120_1: R120.1 R121.2 U24.1 U24.4 | length 7.4
  Top Layer w0.2: R121.2@81.188,57.259 81.188,56.759 81.306,56.642 82.842,56.642 83.225,57.025 83.225,57.306 ; U24.1@83.338,58.381 83.338,57.912 83.225,57.799 83.225,57.306 ; U24.4@84.738,58.381 84.738,57.715 84.33,57.306 83.225,57.306
  Top Layer w0.25: R121.2@81.188,57.259 R120.1@81.188,58.159
NetR123_1: R123.1 R124.2 U25.1 U25.4 | length 8.8
  Top Layer w0.25: R123.1@80.9,64.5 80.9,62.946 v1(81.046,62.8) 83.192,62.8 83.338,62.946 U25.1@83.338,63.381 ; v1(84.4,62.7) 84.407,62.7 84.738,63.031 U25.4@84.738,63.381
  Bottom Layer w0.25: v1(81.046,62.8) 81.087,62.8 81.187,62.7 v1(84.4,62.7)
NetR125_2: R125.2 R126.1 U15.34 | length 4.3
  Top Layer w0.2: R125.2@9.36,60.345 R126.1@9.36,59.438 9.36,58.583 8.977,58.199 8.977,57.566 9.186,57.357 10.27,57.357 U15.34@10.289,57.338
PCIe.CK_1_N: J2.19 J8.11 | length 66.5
  Top Layer w0.19: J8.11@9.257,26.777 9.462,26.982 9.462,27.885 9.487,27.91 9.487,29.847 11.47,31.83 26.651,31.83 28.424,33.603 29.13,33.603 35.399,39.873 35.399,44.378 37.598,46.578 41.122,46.578 44.418,49.873 44.418,52.227 43.924,52.721 43.736,52.721 43.581,52.876 v1(43.576,52.876) ; J2.19@50.41,61.865 50.41,61.071 50.65,60.831 v1(50.65,60.789)
  Bottom Layer w0.19: v1(43.576,52.876) 43.591,52.86 44.678,52.86 45.3,53.482 45.3,55.8 46.86,57.36 49.119,57.36 50.65,58.891 v1(50.65,60.789)
PCIe.CK_1_P: J2.17 J8.13 | length 65.8
  Top Layer w0.19: J8.13@10.057,26.777 9.852,26.982 9.852,27.885 9.827,27.91 9.827,29.706 11.611,31.49 26.792,31.49 28.565,33.263 29.271,33.263 35.739,39.732 35.739,44.238 37.739,46.238 41.263,46.238 44.757,49.732 44.757,52.368 44.157,52.968 44.157,53.156 44.002,53.311 v1(44.002,53.317) ; J2.17@50.01,61.865 50.01,60.671 50.189,60.491 v1(50.189,60.489)
  Bottom Layer w0.19: v1(44.002,53.317) 44.042,53.277 44.144,53.277 44.163,53.258 44.231,53.258 44.288,53.2 44.537,53.2 44.96,53.623 44.96,55.941 46.719,57.7 48.978,57.7 50.189,58.911 v1(50.189,60.489)
PCIe.RST_1: J2.21 J8.22 | length 84.7
  Top Layer w0.2: J8.22@16.857,34.977 17.057,34.777 17.057,33.923 17.48,33.5 17.861,33.5 18.602,32.759 21.041,32.759 v1(21.32,33.038) ; v1(47.639,29.138) 49.06,30.559 v1(50.153,30.559) ; J2.21@50.81,61.865 50.81,61.445 v1(51.106,61.149) ; v1(53.3,34) 53.3,34.8 54.35,35.85 55.883,35.85 56,35.733 v1(56,34.9)
  Bottom Layer w0.2: v1(21.32,33.038) 21.325,33.033 21.325,30.656 22.191,29.79 25.351,29.79 27.316,27.825 41.67,27.825 42.946,29.101 47.602,29.101 v1(47.639,29.138) ; v1(50.153,30.559) 51.759,30.559 52.9,31.7 52.9,33.6 v1(53.3,34) ; v1@51.1,61.149 51.1,57.87 48.968,55.738 46.939,55.738 45.773,54.572 45.773,53.003 55.005,43.772 55.005,36.605 56,35.61 v1(56,34.9)
PCIe.RX_1_N: J2.15 J8.23 | length 64.9
  Top Layer w0.19: J8.23@17.257,26.777 17.462,26.982 17.462,27.885 17.487,27.91 17.487,28.699 17.487,29.319 16.646,30.16 16.646,30.787 16.993,31.135 17.62,31.135 19.289,29.466 19.635,29.466 19.783,29.614 19.783,30.557 20.226,31 23.161,31 27.266,31 28.693,32.427 29.725,32.427 36.599,39.302 36.599,43.378 38.536,45.315 41.984,45.315 46.56,49.891 46.56,52.73 44.304,54.986 43.821,54.986 43.57,54.735 43.57,54.414 43.7,54.284 v1(43.7,54.2) ; v1(49.38,60.401) 49.38,60.417 49.58,60.618 49.58,61.382 49.61,61.412 J2.15@49.61,61.865
  Bottom Layer w0.19: v1(43.7,54.2) 43.66,54.24 43.66,54.342 43.641,54.361 43.641,54.479 43.57,54.549 43.57,55.589 48.331,60.35 48.801,60.35 48.806,60.345 49.175,60.345 49.183,60.353 49.219,60.353 49.227,60.361 49.339,60.361 v1(49.38,60.401)
PCIe.RX_1_P: J2.13 J8.25 | length 65.8
  Top Layer w0.19: J8.25@18.057,26.777 17.852,26.982 17.852,27.885 17.827,27.91 17.827,28.359 17.827,29.46 16.986,30.301 16.986,30.647 17.134,30.795 17.48,30.795 19.149,29.126 19.776,29.126 20.123,29.473 20.123,30.416 20.367,30.66 23.501,30.66 27.407,30.66 28.834,32.087 29.866,32.087 36.939,39.161 36.939,43.238 38.677,44.975 42.125,44.975 46.9,49.75 46.9,52.871 44.445,55.326 43.68,55.326 43.23,54.876 43.23,54.414 43.1,54.284 v1(43.1,54.2) ; v1(48.991,60.79) 48.991,60.841 49.24,61.09 49.24,61.382 49.21,61.412 J2.13@49.21,61.865
  Bottom Layer w0.19: v1(43.1,54.2) 43.14,54.24 43.14,54.342 43.159,54.361 43.159,54.479 43.23,54.549 43.23,55.73 48.19,60.69 48.742,60.69 48.802,60.75 48.95,60.75 v1(48.991,60.79)
PCIe.TX_1_N: J2.11 J8.31 | length 65.8
  Top Layer w0.19: J8.31@20.457,26.777 20.457,27.924 20.687,28.154 20.687,28.631 21.715,29.659 21.786,29.659 25.235,29.659 25.678,29.215 25.678,28.968 25.923,28.724 26.132,28.724 26.376,28.968 26.376,29.215 26.82,29.659 27.408,29.659 27.619,29.87 27.65,29.901 27.65,30.05 v1(27.691,30.09) ; v1(30.089,37.038) 30.089,37.094 30.001,37.182 30.001,37.5 30.299,37.798 32.123,37.798 34.439,40.114 34.439,45.238 37.039,47.838 40.788,47.838 41.976,49.025 41.976,51.12 41.976,54.816 41.532,55.26 41.353,55.26 41.109,55.504 41.109,55.713 41.353,55.958 44.122,55.958 44.565,56.401 44.565,56.892 44.122,57.336 42.57,57.336 42.326,57.58 42.326,57.925 42.661,58.261 44.75,60.35 47.772,60.35 48.755,61.333 48.755,61.357 48.81,61.412 J2.11@48.81,61.865
  Bottom Layer w0.19: v1(27.691,30.09) 27.65,30.05 27.65,29.901 27.422,29.673 27.304,29.673 25.725,31.252 25.725,33.923 26.139,34.338 29.039,34.338 29.984,35.283 29.984,36.876 30.089,36.981 v1(30.089,37.038)
PCIe.TX_1_P: J2.9 J8.33 | length 66.3
  Top Layer w0.19: J8.33@21.257,26.777 21.257,27.924 21.027,28.154 21.027,28.49 21.786,29.249 21.856,29.319 25.094,29.319 25.338,29.075 25.338,28.828 25.782,28.384 26.273,28.384 26.716,28.828 26.716,29.075 26.961,29.319 27.549,29.319 27.619,29.389 27.891,29.661 28.039,29.661 v1(28.08,29.701) ; v1(29.539,37.038) 29.539,37.094 29.636,37.191 29.636,37.615 30.158,38.138 31.982,38.138 34.099,40.254 34.099,45.378 36.898,48.178 40.648,48.178 41.636,49.166 41.636,51.12 41.636,54.675 41.391,54.92 41.213,54.92 40.769,55.363 40.769,55.854 41.213,56.298 43.981,56.298 44.225,56.542 44.225,56.751 43.981,56.996 42.429,56.996 41.986,57.439 41.986,58.066 42.181,58.261 44.609,60.69 47.631,60.69 48.415,61.474 48.415,61.86 J2.9@48.41,61.865
  Bottom Layer w0.19: v1(28.08,29.701) 28.039,29.661 27.891,29.661 27.563,29.333 27.163,29.333 25.385,31.111 25.385,34.064 25.998,34.678 28.898,34.678 29.644,35.423 29.644,36.876 29.539,36.981 v1(29.539,37.038)
PDM.CK_1: J1.66 J4.16 | length 46.2
  Top Layer w0.2: J1.66@49.61,18.685 49.61,19.158 50.523,20.071 50.523,24.607 51.134,25.218 v1(53.879,25.218) ; v1(63.765,25.989) 64.715,25.989 65.983,24.721 73.375,24.721 74.106,25.452 74.106,29.126 75.45,30.47 75.45,32.85 75.1,33.2 75.1,37.6 75.75,38.25 J4.16@76.85,38.25
  Bottom Layer w0.2: v1(53.879,25.218) 54.322,25.661 63.436,25.661 v1(63.765,25.989)
PDM.D0_1: J1.68 J4.17 | length 46.2
  Top Layer w0.2: J1.68@49.21,18.685 49.21,19.267 50.173,20.23 50.173,24.752 51.171,25.75 53.697,25.75 v1(53.706,25.741) ; v1(62.927,26.115) 63.503,25.539 64.444,25.539 65.612,24.371 73.52,24.371 74.456,25.307 74.456,28.776 75.8,30.12 75.8,33.258 75.5,33.558 75.5,36.957 75.793,37.25 J4.17@76.85,37.25
  Bottom Layer w0.2: v1(53.706,25.741) 54.079,26.115 v1(62.927,26.115)
PDM.D1_1: J1.70
PWM0_1: J2.62 J5.33 R69.1 | length 82.6
  Top Layer w0.15: R69.1@22.68,38.615 22.681,38.614 24.275,38.614 25.946,36.943 v1(27.414,36.943) ; v1(28.455,41.065) 30.255,41.065 v1(31.855,39.465) ; v1(49.855,39.465) 52.555,39.465 53.97,38.05 v1(55.603,38.05) ; J2.62@58.81,58.785 58.81,54.881 60.934,52.758 60.934,38.392 60.81,38.268 60.81,37.065 61.85,36.025 v1(61.85,35.35)
  Top Layer w0.2: v1(67.4,35.21) 67.435,35.245 J5.33@69.218,35.245
  Bottom Layer w0.15: v1(27.414,36.943) 28.375,37.905 28.375,38.497 28.828,38.95 28.828,40.692 v1(28.455,41.065) ; v1(31.855,39.465) 31.855,37.981 36.486,33.35 38.34,33.35 39.455,34.465 44.855,34.465 46.744,36.354 46.744,37.208 49,39.465 v1(49.855,39.465) ; v1(55.603,38.05) 60.592,38.05 60.742,38.2 v1(60.81,38.2)
  Bottom Layer w0.2: v1(61.85,35.35) 61.99,35.21 v1(67.4,35.21)
PWM1_1: J2.64 J5.35 R51.1 | length 61.8
  Top Layer w0.15: J2.64@59.21,58.785 59.21,54.906 61.282,52.834 61.282,37.088 62.35,36.02 62.35,34.25 v1(62,33.9) ; v1(76.2,25) 76.635,25.435 80.265,25.435 82.7,23 82.7,19.9 82.3,19.5 R51.1@81.55,19.5
  Top Layer w0.2: J5.35@69.218,33.975 69.193,34 v1(67.603,34) 67.1,33.497 67.1,30.9 67.6,30.4 69.9,30.4 72.276,28.024 v1(72.276,25.904)
  Bottom Layer w0.2: v1(62,33.9) 67.448,33.9 67.548,34 v1(67.603,34) ; v1(72.276,25.904) 73.18,25 v1(76.2,25)
PWM2_1: J2.66 J5.37 R44.1 | length 60.5
  Top Layer w0.15: J2.66@59.61,58.785 59.61,54.93 61.582,52.958 61.582,37.256 62.7,36.138 62.7,33.5 v1(61.9,32.7) ; R44.1@72.8,12.7 72.8,13.153 72.888,13.241 73.575,13.241 73.676,13.342 v1(73.744,13.342)
  Top Layer w0.2: v1(67.601,32.712) 69.211,32.712 J5.37@69.218,32.705 70.815,32.705 70.932,32.588 70.932,30.888 72.912,28.909 v1(72.912,25.974)
  Bottom Layer w0.15: v1(72.912,25.974) 72.557,26.329 72.1,26.329 71.851,26.08 71.851,25.728 73.744,23.835 73.744,13.987 73.755,13.976 73.755,13.624 73.744,13.613 v1(73.744,13.342)
  Bottom Layer w0.2: v1(61.9,32.7) 61.906,32.706 67.595,32.706 v1(67.601,32.712)
PWM3_1: J2.68 J5.39 R63.1 | length 110.8
  Top Layer w0.15: v1(48.778,27.625) 48.846,27.625 48.952,27.732 53.497,27.732 53.807,28.042 53.807,28.918 53.6,29.125 v1(53.6,29.129) ; J2.68@60.01,58.785 60.01,54.954 61.882,53.082 61.882,37.808 63.05,36.64 63.05,31.801 62.95,31.701 v1(62.95,31.62)
  Top Layer w0.2: R63.1@6.605,38.265 6.605,37.771 4.801,35.967 4.801,33.186 5.578,32.409 21.632,32.409 v1(21.986,32.763) ; v1(67.594,31.444) 69.209,31.444 J5.39@69.218,31.435
  Bottom Layer w0.15: v1(21.986,32.763) 21.986,30.539 22.41,30.115 25.486,30.115 27.451,28.15 41.536,28.15 42.812,29.426 43.567,29.426 44.316,30.175 47.515,30.175 48.214,29.476 48.214,28.703 48.8,28.117 48.8,27.647 v1(48.778,27.625) ; v1(53.6,29.129) 53.804,28.925 63.9,28.925 65.094,30.119 65.094,31.55
  Bottom Layer w0.2: v1(62.95,31.62) 63.02,31.55 65.094,31.55 67.433,31.55 67.54,31.444 v1(67.594,31.444)
PWR_IN_12: C116.2 C118.2 C119.2 C120.2 L3.1 PWR_IN.X PWR_IN_1.X PWR_IN_2.X R111.1 X1.1 | length 22.6
  Top Layer w0.2: R111.1@75.041,84.49 v1(75.845,84.49)
  Top Layer w0.3: v1(81.57,82.04) 81.583,82.053 82.97,82.053 82.977,82.06 L3.1@83.375,82.06
  Top Layer w0.8: L3.1@82.97,82.324 C120.2@82.97,84.115 84.761,84.115 ; C119.2@82.97,85.997 84.761,85.997 ; C116.2@82.97,87.879 84.761,87.879 ; C118.2@82.97,89.761 84.761,89.761
  Bottom Layer w0.3: v1(75.845,84.49) 77.632,82.703 78.297,82.703 78.96,82.04 v1(81.57,82.04)
  Bottom Layer w1: PWR_IN_2.X@87,89 87,90.308 87.692,91 X1.1@89.662,91
PWR_ON_1V8_5: Q7.3 U1.15 | length 42.2
  Top Layer w0.2: U1.15@47.85,82.45 47.905,82.505 47.905,83.383 48.722,84.2 v1(49.5,84.2) ; v1(69.122,61.382) 69.124,61.381 69.124,60.461 Q7.3@69.125,60.46
  Bottom Layer w0.2: v1(49.5,84.2) 49.5,83.494 51.37,81.624 51.37,76.457 52.2,75.627 52.2,69.232 53.982,67.45 60.776,67.45 61.36,66.866 61.36,63.56 63.473,61.447 67.975,61.447 68.239,61.71 68.795,61.71 v1(69.122,61.382)
REGN_12: C86.1 R73.2 U11.22 | length 14.7
  Top Layer w0.2: U11.22@91.85,42.335 91.871,42.356 v1@91.871,43.067 ; v1@91.854,43.057 91.95,43.152 C86.1@91.95,43.725
  Top Layer w0.25: v1(94.509,35.046) R73.2@94.509,35.628
  Bottom Layer w0.4: v1(91.893,43.089) 91.447,43.089 89.949,41.591 89.949,38.82 90.769,38 93.7,38 94.503,37.197 94.503,35.052 v1(94.509,35.046)
SAI.CK_1: J2.49 J5.15 | length 30
  Top Layer w0.15: v1(64.488,59.277) 64.492,59.273 64.492,54.565 65.485,53.572 65.485,47.559 66.369,46.675 J5.15@69.218,46.675
  Top Layer w0.2: J2.49@56.41,61.865 56.41,62.174 56.41,65.088 v1(56.424,65.102)
  Bottom Layer w0.15: v1(56.424,65.102) 57.908,65.102 58.216,64.794 58.992,64.794 63.753,60.034 63.899,60.034 64.44,59.492 64.44,59.325 v1(64.488,59.277)
SAI.D0_1: J2.53 J5.19 | length 29.8
  Top Layer w0.15: v1(63.578,59.309) 63.623,59.264 63.623,57.803 63.405,57.585 63.405,54.451 64.5,53.356 64.5,46.403 66.768,44.135 J5.19@69.218,44.135
  Top Layer w0.2: J2.53@57.21,61.865 57.21,63.975 57.385,64.15 v1(57.385,64.204)
  Bottom Layer w0.15: v1(57.385,64.204) 57.394,64.194 58.692,64.194 v1(63.578,59.309)
SAI.D1_1: J2.55 J5.21 | length 29.1
  Top Layer w0.15: v1(63.139,58.874) 63.1,58.835 63.1,54.332 64.2,53.232 64.2,46.215 67.55,42.865 J5.21@69.218,42.865
  Top Layer w0.2: J2.55@57.61,61.865 57.61,63.501 v1(57.876,63.767)
  Bottom Layer w0.15: v1(57.876,63.767) 58.662,63.767 63.139,59.289 v1(63.139,58.874)
SAI.FS_1: J2.51 J5.17 | length 30.2
  Top Layer w0.15: v1(64.064,58.86) 64.064,57.821 63.705,57.461 63.705,54.576 64.8,53.48 64.8,47.135 66.53,45.405 J5.17@69.218,45.405
  Top Layer w0.2: J2.51@56.81,61.865 56.81,64.068 56.879,64.137 v1(56.879,64.668)
  Bottom Layer w0.15: v1(56.879,64.668) 57.842,64.668 58.016,64.494 58.868,64.494 63.629,59.734 63.765,59.734 64.063,59.435 64.063,58.862 v1(64.064,58.86)
SCLK_5: D2.C SIM1.C3 SIM_SCLK.X U1.38 | length 46.2
  Top Layer w0.2: D2.C@55.1,86.4 v1(55.1,88.1) ; v1(60.7,88.55) 60.735,88.515 SIM1.C3@60.735,86.2
  Top Layer w0.25: v1(46.743,67.526) 46.746,67.529 46.746,68.546 U1.38@46.75,68.55
  Bottom Layer w0.2: v1(46.743,67.526) 49.723,70.506 49.723,74.55 44.77,79.503 44.77,85.155 47.706,88.092 55.96,88.092 56.427,88.559 v1@60.7,88.559 ; v1(60.7,88.55) 62.15,90 SIM_SCLK.X@63,90
SDC.CD_1: J1.67 J11.CD1 SDC_CD.X | length 26.9
  Top Layer w0.2: J1.67@49.21,15.605 49.21,12.69 50.9,11 50.9,8.379 v1(50.323,7.802) ; v1(60.352,5.947) 60.368,5.964 60.368,10.781 60.768,11.181 J11.CD1@60.768,12.162
  Bottom Layer w0.2: v1(50.323,7.802) 55.436,7.802 57.29,5.947 58.997,5.947 ; SDC_CD.X@59,5 58.997,5.003 58.997,5.947 ; v1(60.352,5.947) 58.997,5.947
SDC.CLK_1: J1.55 J11.5 SDC_CLK.X | length 18
  Top Layer w0.2: J1.55@51.61,15.605 51.61,13.737 54.059,11.289 v1(54.059,4.997) 54.059,1.252 J11.5@53.918,1.112
  Bottom Layer w0.2: v1(54.059,4.997) 54.059,6.059 SDC_CLK.X@55,7
SDC.CMD_1: J1.57 J11.3 SDC_CMD.X | length 19.8
  Top Layer w0.2: J1.57@51.21,15.605 51.21,13.501 53.597,11.114 53.597,5.718 v1(53.564,5.684) 53.564,5.63 53.461,5.527 v1(53.461,2.585) ; v1(56.095,3.106) 56.095,1.135 J11.3@56.118,1.112
  Bottom Layer w0.2: SDC_CMD.X@53,5 53,5.066 53.564,5.63 v1(53.564,5.684) ; v1(53.461,2.585) 53.981,3.106 v1(56.095,3.106)
SDC.D0_1: J1.59 J11.7 SDC_D0.X | length 16.9
  Top Layer w0.2: J1.59@50.81,15.605 50.81,13.406 53.055,11.161 53.055,3.9 51.718,2.563 J11.7@51.718,1.112
  Bottom Layer w0.2: SDC_D0.X@53,7 53.027,6.973 53.027,6.085 v1(53.055,6.057)
SDC.D1_1: J1.61 J11.8 SDC_D1.X | length 17.4
  Top Layer w0.2: J1.61@50.41,15.605 50.41,13.24 52.342,11.308 v1(52.342,6.207) 52.342,3.942 50.7,2.3 50.7,1.444 J11.8@50.618,1.362
  Bottom Layer w0.2: SDC_D1.X@51,7 51.091,6.909 51.64,6.909 v1(52.342,6.207)
SDC.D2_1: J1.63 J11.1 SDC_D2.X | length 24.1
  Top Layer w0.2: J1.63@50.01,15.605 50.01,13.074 51.83,11.254 51.83,4.24 v1(50.944,3.354) ; v1(57.475,3.939) 57.513,3.901 57.513,3.744 58.044,3.214 58.3,2.958 58.3,1.38 J11.1@58.318,1.362
  Bottom Layer w0.2: v1(50.944,3.354) 50.982,3.392 51.117,3.392 51.161,3.436 53.127,3.436 53.846,4.155 55.006,4.155 ; SDC_D2.X@55,5 55,4.161 55.006,4.155 ; v1(57.475,3.939) 56.889,3.939 56.673,4.155 55.006,4.155
SDC.D3_1: J1.65 J11.2 SDC_D3.X | length 26.1
  Top Layer w0.2: J1.65@49.61,15.605 49.61,12.89 51.398,11.102 51.398,5.672 50.4,4.674 v1(50.4,2.823) ; v1(57.169,3.11) 57.169,1.411 J11.2@57.218,1.362
  Bottom Layer w0.2: v1(50.4,2.823) 52.169,2.823 52.389,3.044 53.343,3.044 53.971,3.672 56.661,3.672 57.169,3.164 v1(57.169,3.11) 57.174,3.115 57.669,3.115 58.046,3.492 58.046,4.079 57.125,5 SDC_D3.X@57,5
SDC.RST_1: J1.71
SDC.WP_1: J1.69
SERIAL0.CTS_1: J1.40 SERIAL0_CTS.X U4.6 | length 34.4
  Top Layer w0.15: U4.6@79.725,17.35 80.582,17.35 80.832,17.6 v1(80.9,17.6)
  Top Layer w0.2: v1(54.515,21.848) 54.81,21.553 J1.40@54.81,18.685
  POWER w0.15: v1(70.146,18.195) 70.722,18.772 79.372,18.772 80.544,17.6 v1(80.9,17.6)
  Bottom Layer w0.15: v1(54.515,21.848) 54.539,21.824 56.351,21.824 56.87,22.344 67.277,22.344 69.847,19.773 69.847,19.153 70.098,18.902 70.098,18.243 v1(70.146,18.195)
SERIAL0.RTS_1: J1.38 SERIAL0_RTS.X U4.21 | length 30.6
  Top Layer w0.15: v1(70.963,14.462) 72.851,16.35 U4.21@74.875,16.35
  Top Layer w0.2: J1.38@55.21,18.685 55.21,20.645 55.771,21.206 55.771,21.653 55.677,21.747 v1(55.677,22.249)
  Bottom Layer w0.15: v1(55.677,22.249) 56.35,22.249 56.745,22.644 68.356,22.644 69.971,21.029 70.963,20.037 v1(70.963,14.462)
SERIAL0.RX_1: J1.36 SERIAL0_RX.X U4.7 U16.3 | length 57.1
  Top Layer w0.15: v1(66.269,23.172) 66.327,23.172 66.482,23.327 73.926,23.327 75.775,25.176 76.024,25.425 76.334,25.735 80.389,25.735 83,23.124 83,18.823 82.215,18.038 80.438,18.038 80.25,17.85 U4.7@79.725,17.85
  Top Layer w0.2: U16.3@55.223,35.342 55.216,35.334 54.686,35.334 54.383,35.031 54.383,30.822 53.852,30.292 53.852,29.562 56.3,27.114 v1@56.3,22.687 ; J1.36@55.61,18.685 55.61,20.52 56.157,21.068 v1(56.157,22.687)
  Bottom Layer w0.15: v1(56.157,22.687) 56.414,22.944 63.696,22.944 63.925,23.172 v1(66.269,23.172) 66.269,23.221 67,23.952 SERIAL0_RX.X@67,24
SERIAL0.TX_1: J1.34 SERIAL0_TX.X U4.22 U19.3 | length 41.4
  Top Layer w0.15: v1(70.97,13.814) 73.006,15.85 U4.22@74.875,15.85
  Top Layer w0.2: v1(55.077,31.885) 55.077,31.847 55.27,31.654 55.27,31.252 U19.3@55.223,31.205 ; J1.34@56.01,18.685 56.01,20.213 56.12,20.323 v1(56.12,20.372) 56.15,20.402 56.15,20.566 56.65,21.066 56.65,29.477 56.19,29.937 56.171,29.937 56.096,30.012 v1(56.041,30.012)
  Bottom Layer w0.15: v1(56.12,20.372) 56.12,21.15 57.014,22.044 66.986,22.044 68,21.03 68,20 68,19.017 70,17.017 SERIAL0_TX.X@70,17 ; SERIAL0_TX.X@69.933,16.837 70.005,16.765 70.005,14.778 v1(70.97,13.814)
  Bottom Layer w0.2: v1(55.077,31.885) 55.077,31.874 55.37,31.58 55.37,30.683 v1(56.041,30.012)
SERIAL1.CTS_1: J1.39 SERIAL1_CTS.X U20.3 | length 74.3
  Top Layer w0.15: J1.39@54.81,15.605 54.81,16.812 55.547,17.549 57.694,17.549 58.182,18.036 62.738,18.036 63.239,18.538 63.239,21.838 60.612,24.465 60.612,28.225 63.436,31.049 63.436,38.233 v1(64.13,38.927) ; v1(83.219,42.388) 82.904,42.388 82.603,42.688 82.603,48.573 v1(83.219,49.188) ; v1(90.06,48.635) 90.068,48.643 90.793,48.643 U20.3@90.8,48.65
  POWER w0.15: v1(78.564,38.093) 78.905,38.433 79.264,38.433 82.794,41.963 82.794,42.014 83.168,42.388 v1(83.219,42.388) ; v1(83.219,49.188) 83.266,49.236 83.456,49.236 84.159,49.938 88.758,49.938 v1(90.06,48.635)
  Bottom Layer w0.15: v1(64.13,38.927) 64.161,38.958 64.338,38.958 64.343,38.963 64.994,38.963 65.79,38.166 78.351,38.166 78.377,38.141 78.516,38.141 v1(78.564,38.093) ; SERIAL1_CTS.X@89,52 90.06,50.94 v1(90.06,48.635)
SERIAL1.RTS_1: J1.37 SERIAL1_RTS.X U22.3 | length 73.8
  Top Layer w0.15: J1.37@55.21,15.605 55.21,16.662 55.797,17.249 57.887,17.249 58.374,17.736 62.871,17.736 63.539,18.405 63.539,21.962 60.912,24.59 60.912,28.041 63.745,30.875 63.745,37.764 v1(64.519,38.538) ; v1(83.219,41.838) 82.879,41.838 82.275,42.442 82.275,48.963 83.002,49.69 83.171,49.69 v1(83.219,49.738) ; v1(90.11,52.347) 90.111,52.348 90.798,52.348 U22.3@90.8,52.35
  POWER w0.15: v1(79.211,38.008) 79.263,38.008 83.045,41.79 83.171,41.79 v1(83.219,41.838) ; v1(83.219,49.738) 83.514,49.738 84.014,50.238 88.001,50.238 v1(90.11,52.347)
  Bottom Layer w0.15: v1(64.519,38.538) 65.214,37.842 71.852,37.842 72.595,37.099 77.387,37.099 77.946,37.658 78.821,37.658 79.171,38.008 v1(79.211,38.008) ; SERIAL1_RTS.X@89,54 90.11,52.89 v1(90.11,52.347)
SERIAL1.RX_1: J1.35 SERIAL1_RX.X U8.3 U16.1 | length 88.8
  Top Layer w0.15: v1(55.219,32.838) 55.223,32.843 U16.1@55.223,33.442 ; J1.35@55.61,15.605 55.61,16.537 56.019,16.946 58.065,16.946 58.555,17.436 63.238,17.436 64.239,18.438 64.239,21.759 61.392,24.607 61.392,28.06 64.212,30.88 64.212,30.989 v1(64.259,31.037) 64.259,31.105 64.185,31.18 64.185,37.535 64.419,37.77 v1(64.419,37.837) ; v1(83.219,41.288) 82.748,41.288 81.975,42.061 81.975,49.324 82.939,50.288 v1(83.219,50.288) ; v1(90.05,56.05) U8.3@90.8,56.05
  POWER w0.15: v1(78.843,37.225) 78.891,37.273 79.086,37.273 83.009,41.196 83.059,41.196 83.151,41.288 v1(83.219,41.288) ; v1(83.219,50.288) 83.522,50.288 83.772,50.538 87.54,50.538 90.05,53.048 v1(90.05,56.05)
  Bottom Layer w0.15: v1(55.219,32.838) 55.548,32.508 55.548,31.862 55.959,31.451 55.959,30.819 56.978,29.8 63.022,29.8 v1(64.259,31.037) ; v1(64.419,37.837) 64.467,37.79 64.843,37.79 65.094,37.538 71.509,37.538 72.283,36.764 77.477,36.764 77.941,37.228 78.293,37.228 ; 78.296,37.225 v1(78.843,37.225) ; SERIAL1_RX.X@89,56 89.025,56.025 90.025,56.025 v1(90.05,56.05)
SERIAL1.TX_1: J1.33 SERIAL1_TX.X U19.1 U21.3 | length 89.4
  Top Layer w0.15: J1.33@56.01,15.605 56.01,16.468 56.188,16.646 58.273,16.646 58.74,17.113 63.347,17.113 64.545,18.311 64.545,21.886 61.692,24.739 61.692,27.659 v1(63.526,29.494) 64.744,30.711 v1(64.744,37.238) ; v1(83.219,40.738) 82.719,40.738 81.675,41.782 81.675,49.592 82.921,50.838 v1(83.219,50.838) ; v1(90.04,59.751) U21.3@90.8,59.75
  Top Layer w0.2: U19.1@55.223,29.305 55.88,29.305 55.96,29.386 v1(56.014,29.386)
  POWER w0.15: v1(78.117,36.803) 78.12,36.8 79.046,36.8 82.951,40.705 83.185,40.705 v1(83.219,40.738) ; v1(83.219,50.838) 87.245,50.838 89.561,53.154 89.561,59.272 v1(90.04,59.751)
  Bottom Layer w0.15: v1(64.744,37.238) 70.133,37.238 70.907,36.464 77.71,36.464 78.049,36.803 v1(78.117,36.803) ; SERIAL1_TX.X@89,58 90.04,59.04 v1(90.04,59.751)
  Bottom Layer w0.2: v1(56.014,29.386) 63.364,29.386 63.472,29.494 v1(63.526,29.494)
SERIAL2.CTS_1: J2.32
SERIAL2.RTS_1: J2.30
SERIAL2.RX_1: J2.28 SERIAL2_RX.X U15.42 | length 56.5
  Top Layer w0.15: U15.42@10.289,53.338 11.962,53.338 12.55,52.75 v1(17,52.75) ; v1(22.5,60.9) 22.5,62.991 v1(22.972,63.463) ; v1(45.102,59.579) 45.33,59.808 51.53,59.808 52.01,59.327 J2.28@52.01,58.785
  POWER w0.15: v1(22.972,63.463) 23.339,63.463 25.476,65.6 30.005,65.6 30.054,65.551 30.258,65.551 v1(30.305,65.503)
  Bottom Layer w0.15: v1(17,52.75) 17.048,52.798 17.177,52.798 18.22,53.841 18.22,56.571 17.425,57.366 17.425,58.649 18.976,60.2 21.8,60.2 v1(22.5,60.9) ; v1(30.305,65.503) 30.305,65.476 30.716,65.066 30.716,64.749 36.464,59 SERIAL2_RX.X@41,59 41.579,59.579 v1(45.102,59.579)
SERIAL2.TX_1: J2.26 SERIAL2_TX.X U15.43 | length 57.7
  Top Layer w0.15: U15.43@10.289,52.838 11.687,52.838 12.325,52.2 17.375,52.2 v1(17.45,52.275) ; v1(23,60.4) 23,62.632 23.2,62.832 v1(23.2,62.9) ; v1(44.858,58.975) 45.098,58.975 45.631,59.508 51.373,59.508 51.61,59.271 J2.26@51.61,58.785
  POWER w0.15: v1(23.2,62.9) 25.6,65.3 29.881,65.3 v1(30.291,64.89)
  Bottom Layer w0.15: v1(17.45,52.275) 18.615,53.44 18.615,56.601 17.725,57.491 17.725,58.524 19.001,59.8 22.4,59.8 v1(23,60.4) ; v1(30.291,64.89) 30.338,64.842 30.338,64.702 38.04,57 SERIAL2_TX.X@41,57 42.975,58.975 v1(44.858,58.975)
SERIAL3.CTS_1: J2.31 J5.30 | length 44.5
  Top Layer w0.15: J2.31@52.81,61.865 52.81,61.443 53.773,60.48 53.957,60.48 v1(53.984,60.453) ; v1(57.575,55.018) 60.135,52.459 v1(60.135,40.695)
  Top Layer w0.2: J5.30@73.282,37.785 74.79,37.785 75.539,38.534 75.539,40.423 v1(75.525,40.438)
  Bottom Layer w0.2: v1(53.984,60.453) 54.468,59.969 54.468,58.03 55.955,56.543 56.047,56.543 57.572,55.018 v1(57.575,55.018) ; v1(60.135,40.695) 60.377,40.938 75.025,40.938 v1(75.525,40.438)
SERIAL3.RTS_1: J2.29 J5.28 | length 44.4
  Top Layer w0.15: J2.29@52.41,61.865 52.41,61.366 53.666,60.109 v1(53.869,59.907) ; v1(58.354,54.885) 58.382,54.885 60.606,52.661 60.606,40.459 v1(60.142,39.995)
  Top Layer w0.19: J5.28@73.282,39.055 74.957,39.055 75.039,39.138 v1(75.039,39.838)
  Bottom Layer w0.15: v1(53.869,59.907) 54.111,59.665 54.111,57.867 57.504,54.474 57.943,54.474 v1(58.354,54.885)
  Bottom Layer w0.19: v1(60.142,39.995) 60.606,40.459 74.418,40.459 v1(75.039,39.838)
